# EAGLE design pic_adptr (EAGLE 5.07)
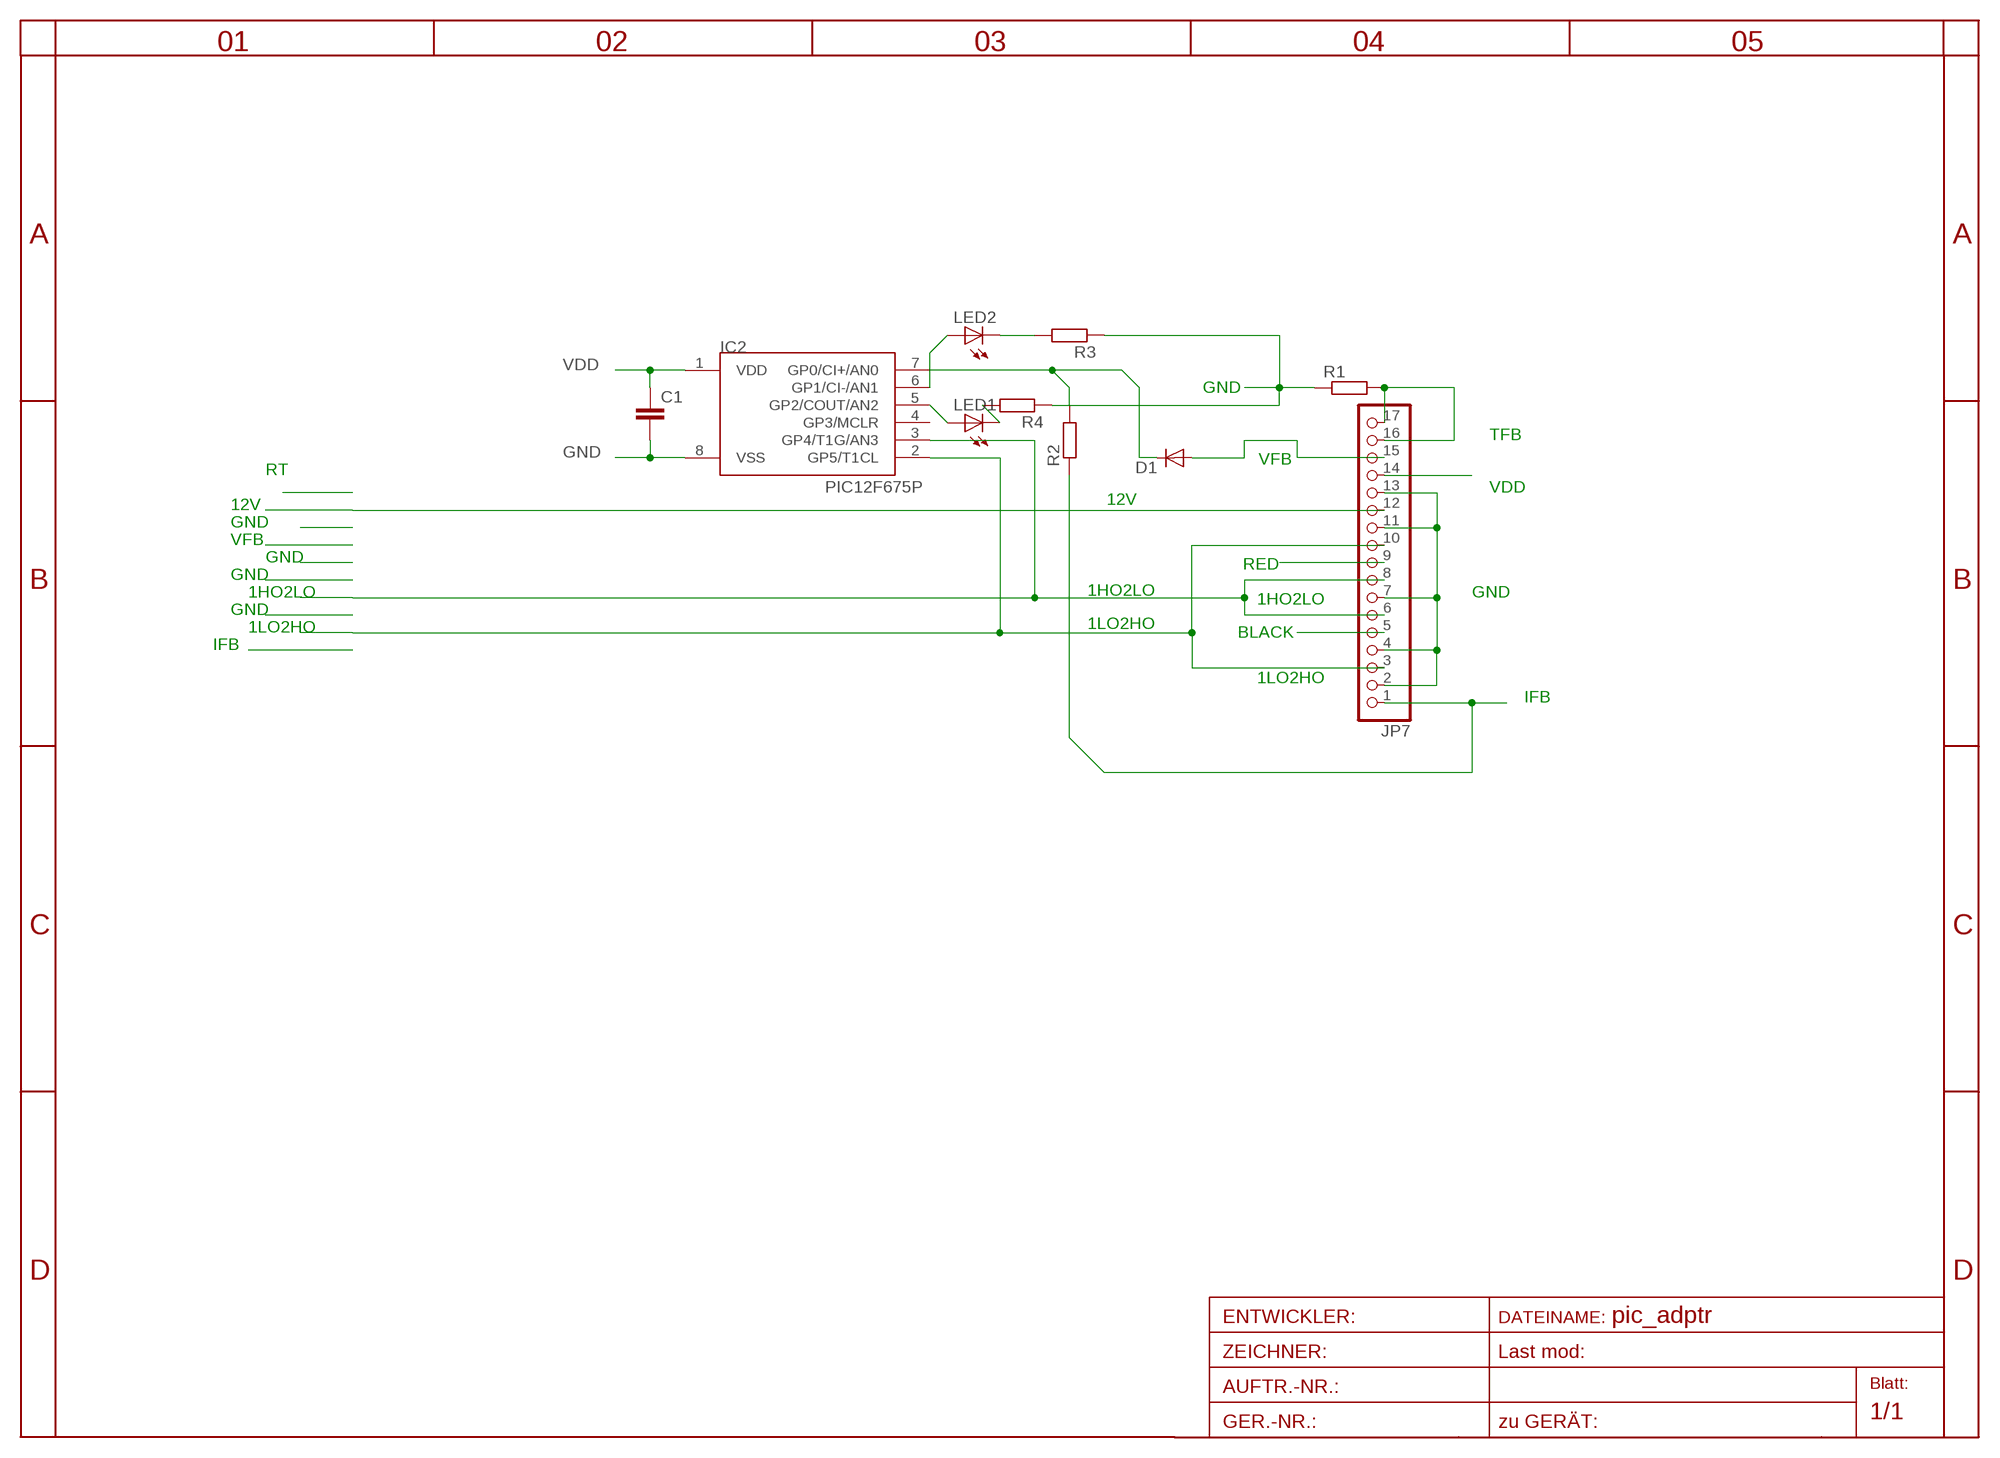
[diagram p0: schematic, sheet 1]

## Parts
C1  C-EUC0805  [C0805]
D1  DIODE-MINIMELF  [MINIMELF]
IC2  PIC12F675P  [DIL8]
JP7  PINHD-1X17  [1X17]
LED1  LEDCHIPLED_1206  [CHIPLED_1206]
LED2  LEDCHIPLED_1206  [CHIPLED_1206]
R1  R-EU_R0805  [R0805]
R2  R-EU_R0805  [R0805]
R3  R-EU_R0805  [R0805]
R4  R-EU_R0805  [R0805]

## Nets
1HO2LO: IC2.3(GP4/T1G/AN3) JP7.6 JP7.8
1LO2HO: IC2.2(GP5/T1CL) JP7.3 JP7.10
12V: JP7.12
BLACK: JP7.5
GND: C1.2 IC2.8(VSS) JP7.2 JP7.4 JP7.7 JP7.11 JP7.13 R1.1 R3.1 R4.1
IFB: JP7.1 R2.1
N$1: IC2.5(GP2/COUT/AN2) LED1.A
N$2: LED1.C R4.2
N$3: IC2.6(GP1/CI-/AN1) LED2.A
N$4: LED2.C R3.2
N$5: D1.C IC2.7(GP0/CI+/AN0) R2.2
RED: JP7.9
TFB: JP7.16 JP7.17 R1.2
VDD: C1.1 IC2.1(VDD) JP7.14
VFB: D1.A JP7.15
Unconnected: IC2.4(GP3/MCLR)

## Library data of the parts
C1 = rcl:C-EU: CAPACITOR, European symbol
D1 = diode:DIODE-: DIODE
IC2 = microchip-5:PIC12F6*: uPC nW 1k Program Flash memory 2x Timer Comparator 10b A/D converter/ 4xIN
JP7 = pinhead:PINHD-1X17: PIN HEADER
LED1 LED2 = led:LED: LED
R1-R4 = rcl:R-EU_: RESISTOR, European symbol

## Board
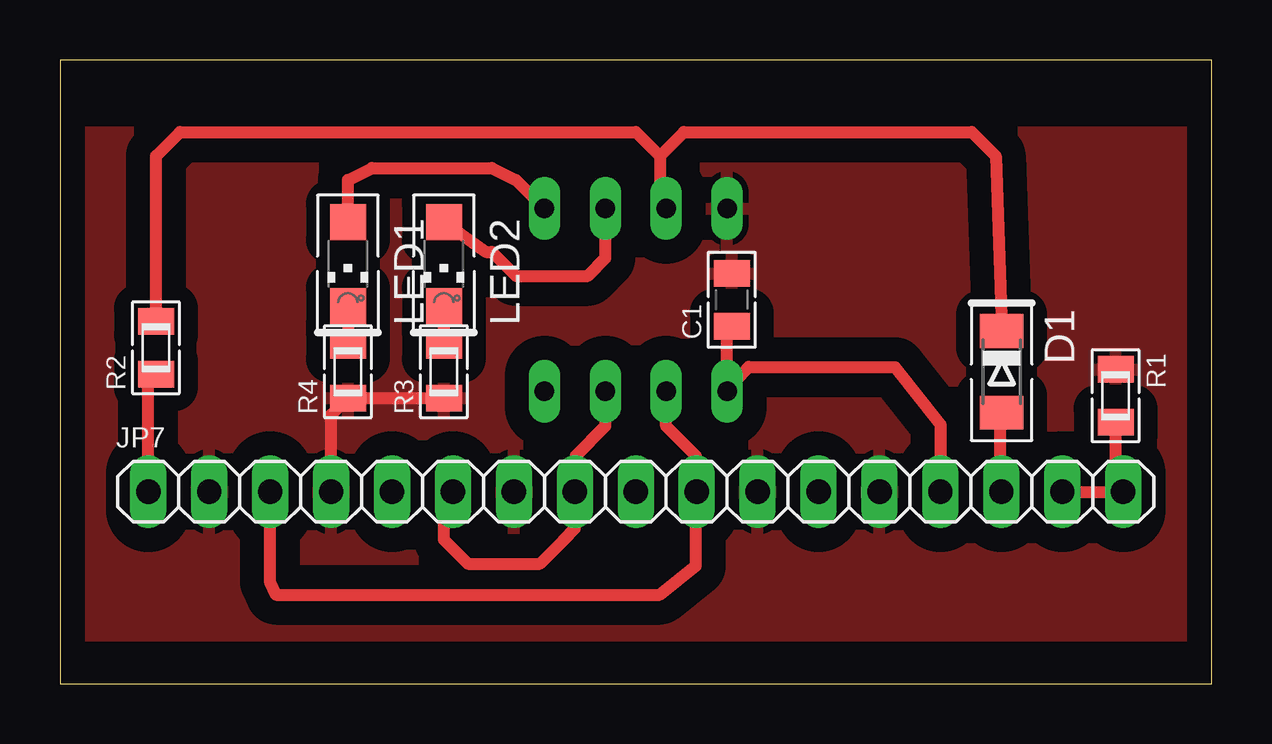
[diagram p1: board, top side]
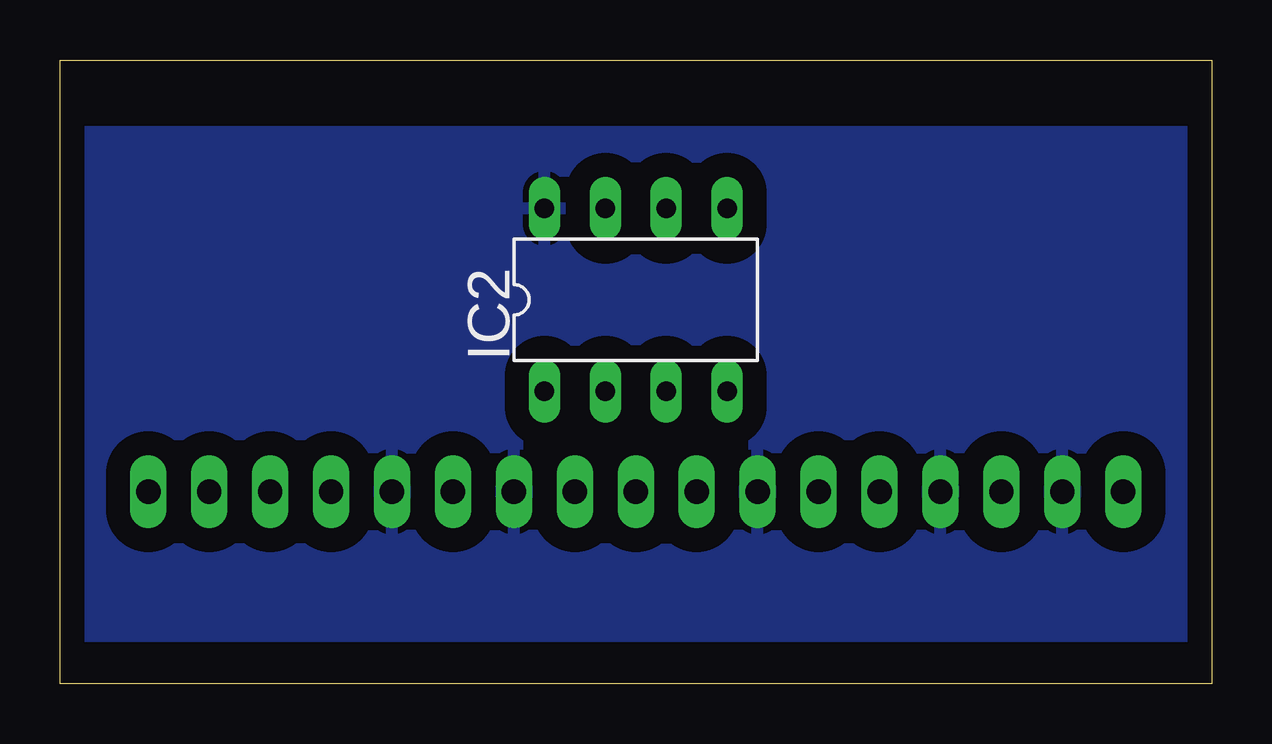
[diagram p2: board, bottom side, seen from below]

Size 48 x 26 mm. Coordinates in mm from the lower left corner, seen from the top.
Outline: 0,0 48,0 48,26 0,26 0,0
Copper layers (1*16): Top 0.035mm / dielectric 1.5mm / Bottom 0.035mm
Design rules "default *": minimum track width 10mil, minimum drill 20mil, track to track 8mil, track to pad 8mil, pad to pad 8mil, via to via 8mil, smd to smd 8mil, copper to edge 40mil, drill to drill 8mil, minimum pad ring 10mil, minimum via ring 8mil, stop-mask expansion 4mil, vias tented up to drill 0mil, thermal gap 10mil

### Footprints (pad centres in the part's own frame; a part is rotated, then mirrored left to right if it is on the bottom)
C0805 = smd 1.1 x 1.5: 1 -1.1,0; 2 1.1,0
MINIMELF = smd 1.4 x 1.8: A 1.7,0; C -1.7,0
DIL8 = drill 0.8 long: 1 -3.81,-3.81; 2 -1.27,-3.81; 3 1.27,-3.81; 4 3.81,-3.81; 5 3.81,3.81; 6 1.27,3.81; 7 -1.27,3.81; 8 -3.81,3.81
1X17 = drill 1.016 long: 1 -20.32,0; 2 -17.78,0; 3 -15.24,0; 4 -12.7,0; 5 -10.16,0; 6 -7.62,0; 7 -5.08,0; 8 -2.54,0; 9 0,0; 10 2.54,0; 11 5.08,0; 12 7.62,0; 13 10.16,0; 14 12.7,0; 15 15.24,0; 16 17.78,0; 17 20.32,0
CHIPLED_1206 = smd 1.5 x 1.5: A 0,-1.75; C 0,1.75
R0805 = smd 1.1 x 1.5: 1 -1.1,0; 2 1.1,0

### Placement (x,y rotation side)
C1  28,16 90 top
D1  39.25,13 270 top
IC2  24,16 0 bottom
JP7  24,8 0 top
LED1  12,17.5 180 top
LED2  16,17.5 180 top
R1  44,12 270 top
R2  4,14 90 top
R3  16,13 90 top
R4  12,13 90 top

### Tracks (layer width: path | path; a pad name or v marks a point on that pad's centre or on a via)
1HO2LO
  Top 0.5: IC2.3 22.73,10.73 21.5,9.5 21.5,8.44 JP7.8 21.46,6.46 21,6 20,5 17,5 16,6 16,7.62 JP7.6
1LO2HO
  Top 0.5: IC2.2 25.27,10.73 26.5,9.5 26.5,8.04 JP7.10 26.5,7.44 26.5,4.9 25,3.7 9,3.7 8.76,4.24 JP7.3
GND
  Top 0.5: JP7.4 11.3,11.2 R4.1 R3.1
  pour Bottom (isolate 1): 1,23 47,23 47,2 1,2
  pour Top (isolate 1): 1,23 47,23 47,2 1,2
IFB
  Top 0.5: JP7.1 3.68,12.58 R2.1
N$1
  Top 0.5: IC2.5 19,21 18,21.5 13,21.5 12,21 LED1.A
N$2
  Top 0.5: LED1.C R4.2
N$3
  Top 0.5: IC2.6 22.73,17.73 22,17 19,17 18,18 17.75,18 LED2.A
N$4
  Top 0.5: R3.2 LED2.C
N$5
  Top 0.5: R2.2 4,22 5,23 24,23 25,22 | 25,22 25,20.08 IC2.7 | D1.C 39,22 38,23 26,23 25,22
TFB
  Top 0.5: R1.2 44,8.32 JP7.17 JP7.16
VDD
  Top 0.5: JP7.14 36.7,8.5 36.7,10.8 34.81,13.19 29.19,13.19 28.7,13.2 IC2.1 27.81,14.71 C1.1
VFB
  Top 0.5: D1.A 39.2,10.7 39.2,8.94 JP7.15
